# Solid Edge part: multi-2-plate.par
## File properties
Author: Deepak Maini
Template: normal.par
Last saved by: Robert a Rhodes jr
Revision: 4
Application: Solid Edge
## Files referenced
..\multi-cutout.asm
6C:\solid-edge-14\c09-sldedg-14-032504\multi-cutout.asm
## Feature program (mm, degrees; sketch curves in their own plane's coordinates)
sketch for "unnamed Protrusion 1" plane through (0, 0, 0) normal (0, 0, 1) x-axis (1, 0, 0)
  line (-46.224, -15.84) -> (-46.224, 16.704)
  line (-46.224, 16.704) -> (47.664, 16.704)
  line (47.664, 16.704) -> (47.664, -15.84)
  line (47.664, -15.84) -> (-46.224, -15.84)
extrude "unnamed Protrusion 1" add finite 10.6 along +normal
extrude "unnamed Cutout 1" cut through
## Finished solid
Body 1: solid body, 7 faces, 14 edges, 8 vertices.
  Faces by surface: plane 6, cylinder 1
  Edges by curve: line 12, circle 2
Bounding box of the edges (mm): 93.888 x 32.544 x 10.600, from (-46.224, -15.84, 0) to (47.664, 16.704, 10.6).
Cylindrical faces by radius (mm): R9.0308 x1
Planar faces by outward normal: +x 1, +y 1, +z 1, -x 1, -y 1, -z 1
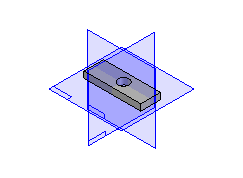
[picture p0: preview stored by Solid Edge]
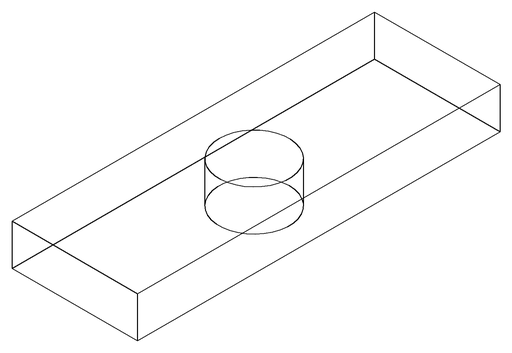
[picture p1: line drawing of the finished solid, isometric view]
